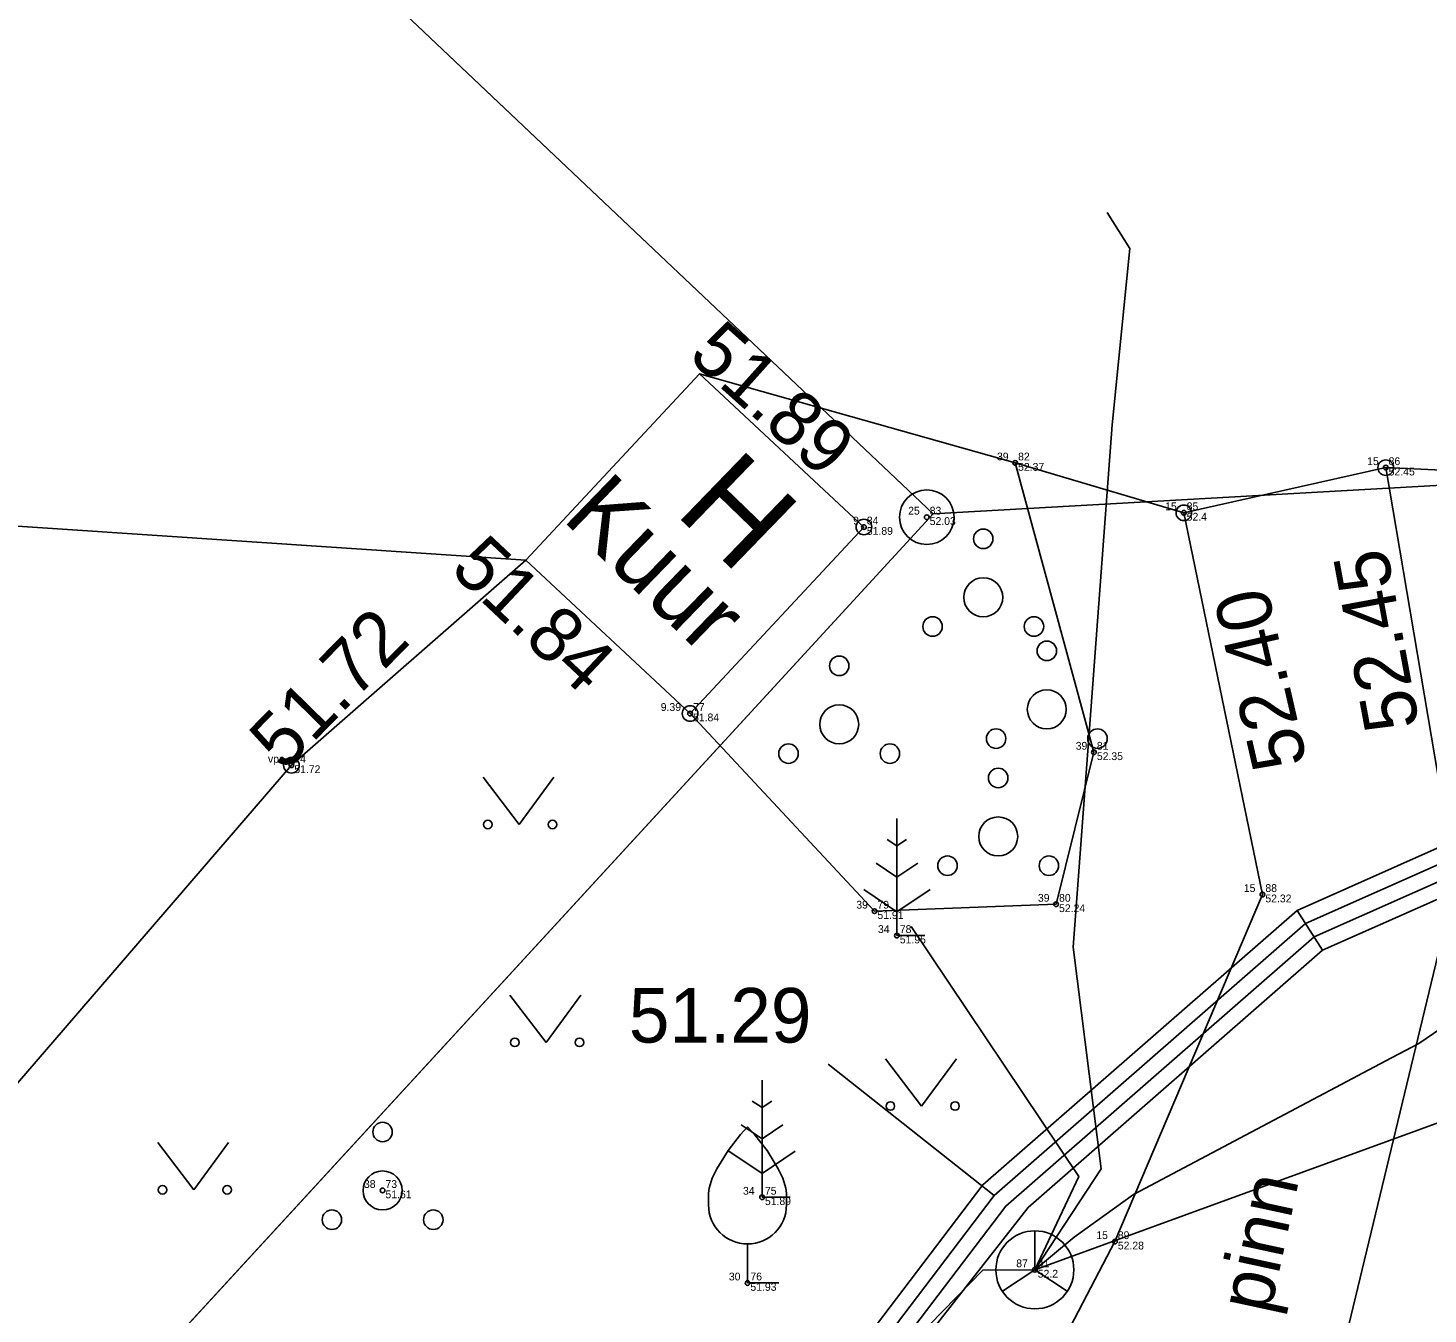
# Model space of a CAD drawing. Extents: x 543497 to 552146, y 6567125 to 6579845.
# Drawn here: x 546496.42 to 546514.37, y 6577831.22 to 6577847.71 of the extents above; entities that cross this region are included whole.
import ezdxf

# ---------------------------------------------------------------- set-up
doc = ezdxf.new("R2010")
doc.units = 0
for name, color, linetype in [('xref_Kangru tee 1_geodeesia$0$ABIJOONIS', 7, 'Continuous'), ('xref_Kangru tee 1_geodeesia$0$ELRAJATISMA', 7, 'Continuous'), ('xref_Kangru tee 1_geodeesia$0$HALJASTUS', 7, 'Continuous'), ('xref_Kangru tee 1_geodeesia$0$HOONE', 7, 'Continuous'), ('xref_Kangru tee 1_geodeesia$0$korgus-EH2000', 7, 'Continuous'), ('xref_Kangru tee 1_geodeesia$0$mootkood', 7, 'Continuous'), ('xref_Kangru tee 1_geodeesia$0$MOOTKORG-eh2000', 7, 'Continuous'), ('xref_Kangru tee 1_geodeesia$0$mootmpunkt', 7, 'Continuous'), ('xref_Kangru tee 1_geodeesia$0$MOOTNR', 7, 'Continuous'), ('xref_Kangru tee 1_geodeesia$0$MOOTPIIR', 7, 'Continuous'), ('xref_Kangru tee 1_geodeesia$0$MPKAABEL', 7, 'Continuous'), ('xref_Kangru tee 1_geodeesia$0$PIIR', 7, 'Continuous'), ('xref_Kangru tee 1_geodeesia$0$PIIRIMLEITUD', 7, 'Continuous'), ('xref_Kangru tee 1_geodeesia$0$PUU', 7, 'Continuous'), ('xref_Kangru tee 1_geodeesia$0$SIKAEV', 7, 'Continuous'), ('xref_Kangru tee 1_geodeesia$0$SITRASS', 7, 'Continuous'), ('xref_Kangru tee 1_geodeesia$0$TEE', 7, 'Continuous')]:
    doc.layers.add(name, color=color, linetype=linetype)

# ---------------------------------------------------------------- blocks, each defined once
blk = doc.blocks.new('xref_Kangru tee 1_geodeesia$0$SIKAEV')
for p, q in [((0, 1), (0, 0)), ((0, 0), (-0.83, -0.55)), ((0, 0), (0.83, -0.55))]:
    blk.add_line(p, q)
blk.add_circle((0, 0), 1)
blk = doc.blocks.new('xref_Kangru tee 1_geodeesia$0$PQQSAS')
for centre, radius in [((0, 1.5), 0.25), ((0, 0), 0.5), ((-1.3, -0.75), 0.25), ((1.3, -0.75), 0.25)]:
    blk.add_circle(centre, radius)
blk = doc.blocks.new('xref_Kangru tee 1_geodeesia$0$mand1')
for p, q in [((0, 3), (0, 0)), ((0, 2.3), (-0.249, 2.466)), ((0.249, 2.466), (0, 2.3)), ((0, 1.5), (-0.533, 1.855)), ((0.533, 1.855), (0, 1.5)), ((-0.849, 1.179), (0, 0.613)), ((0, 0.613), (0.849, 1.179)), ((0.72, 0), (0, 0))]:
    blk.add_line(p, q)
blk = doc.blocks.new('xref_Kangru tee 1_geodeesia$0$VILJA1')
for p, q in [((0, 0), (0, 1)), ((0.8, 0), (0, 0))]:
    blk.add_line(p, q)
for points in [[(-1, 2), (-1, 2.3), (-0.98, 2.43), (-0.91, 2.69), (-0.79, 2.93), (-0.5, 3.4), (-0.18, 3.81), (0, 4)], [(1, 2), (1, 2.3), (0.98, 2.43), (0.91, 2.69), (0.79, 2.93), (0.5, 3.4), (0.18, 3.81), (0, 4)]]:
    blk.add_lwpolyline(points)
blk.add_arc((0, 2), 1, 180, 0)
blk = doc.blocks.new('xref_Kangru tee 1_geodeesia$0$PMTORU')
blk.add_circle((0, 0), 0.7)
blk = doc.blocks.new('xref_Kangru tee 1_geodeesia$0$MURU')
for p, q in [((-0.927, 1.213), (0, 0)), ((0, 0), (0.891, 1.213))]:
    blk.add_line(p, q)
for centre in [(-0.802, 0), (0.856, 0)]:
    blk.add_circle(centre, 0.11)

msp = doc.modelspace()

# ---------------------------------------------------------------- linework, layer by layer
at = {"layer": 'xref_Kangru tee 1_geodeesia$0$ABIJOONIS'}
msp.add_lwpolyline([(546508.812, 6577832.742), (546506.684, 6577834.424)], dxfattribs=at)
at = {"layer": 'xref_Kangru tee 1_geodeesia$0$ELRAJATISMA'}
for points in [[(546512.696, 6577836.397), (546514.646, 6577837.264), (546525.645, 6577845.5), (546527.137, 6577846.751), (546527.843, 6577846.56), (546526.018, 6577845.029), (546514.952, 6577836.743), (546513.022, 6577835.886), (546512.696, 6577836.397)], [(546504.478, 6577826.48), (546507.219, 6577830.975), (546508.665, 6577832.879), (546512.696, 6577836.397), (546513.022, 6577835.886), (546509.246, 6577832.59), (546507.715, 6577830.636), (546504.991, 6577826.168), (546503.121, 6577825.158), (546503.766, 6577826.25), (546504.478, 6577826.48)]]:
    msp.add_lwpolyline(points, dxfattribs=at)
at = {"layer": 'xref_Kangru tee 1_geodeesia$0$HALJASTUS'}
for points in [[(546504.912, 6577838.921), (546507.277, 6577836.387), (546509.606, 6577836.475), (546510.091, 6577838.424), (546509.081, 6577842.133)], [(546483.928, 6577831.007), (546484.106, 6577832.259), (546490.129, 6577827.047), (546499.799, 6577838.257), (546502.804, 6577840.886)]]:
    msp.add_lwpolyline(points, dxfattribs=at)
at = {"layer": 'xref_Kangru tee 1_geodeesia$0$HOONE'}
msp.add_lwpolyline([(546505.033, 6577843.277), (546507.141, 6577841.312), (546504.912, 6577838.921), (546502.804, 6577840.886)], dxfattribs=at)
at = {"layer": 'xref_Kangru tee 1_geodeesia$0$korgus-EH2000'}
for centre in [(546513.833, 6577842.073), (546511.243, 6577841.494), (546507.141, 6577841.312), (546504.912, 6577838.921), (546499.799, 6577838.257)]:
    msp.add_circle(centre, 0.1, dxfattribs=at)
at = {"layer": 'xref_Kangru tee 1_geodeesia$0$mootmpunkt'}
for centre in [(546509.081, 6577842.133), (546513.833, 6577842.073), (546507.947, 6577841.438), (546511.243, 6577841.494), (546507.141, 6577841.312), (546504.912, 6577838.921), (546510.091, 6577838.424), (546499.799, 6577838.257), (546512.252, 6577836.6), (546507.277, 6577836.387), (546509.606, 6577836.475), (546507.564, 6577836.074), (546500.968, 6577832.806), (546505.834, 6577832.719), (546510.36, 6577832.15), (546509.333, 6577831.789), (546505.648, 6577831.62)]:
    msp.add_circle(centre, 0.03, dxfattribs=at)
at = {"layer": 'xref_Kangru tee 1_geodeesia$0$MOOTPIIR'}
msp.add_lwpolyline([(546524.807, 6577818.824), (546524.335, 6577820.155), (546523.257, 6577825.159), (546523.628, 6577826.051), (546521.953, 6577833.502), (546521.112, 6577836.894), (546520.061, 6577840.252), (546519.084, 6577842.675), (546518.786, 6577842.498), (546518.339, 6577842.354), (546515.541, 6577841.994), (546513.833, 6577842.073), (546511.243, 6577841.494), (546509.081, 6577842.133), (546505.033, 6577843.277), (546502.804, 6577840.886), (546478.391, 6577842.519)], dxfattribs=at)
at = {"layer": 'xref_Kangru tee 1_geodeesia$0$MPKAABEL'}
for points in [[(546527.321, 6577847.419), (546527.372, 6577846.687), (546525.769, 6577845.343), (546514.748, 6577837.09), (546512.804, 6577836.227), (546508.812, 6577832.742), (546507.384, 6577830.862), (546504.649, 6577826.376), (546503.269, 6577825.399)], [(546503.758, 6577826.154), (546504.82, 6577826.272), (546507.549, 6577830.749), (546508.959, 6577832.605), (546512.913, 6577836.056), (546514.85, 6577836.916), (546525.893, 6577845.186), (546527.457, 6577846.497), (546527.52, 6577846.865)]]:
    msp.add_lwpolyline(points, dxfattribs=at)
at = {"layer": 'xref_Kangru tee 1_geodeesia$0$PIIR'}
for points in [[(546044, 6578353.3), (546163.95, 6578208.05), (546259.8, 6578095.33), (546272.31, 6578081.21), (546307.56, 6578041.43), (546352.17, 6578005.12), (546393.84, 6577964.11), (546469.41, 6577900.33), (546488.79, 6577882.98), (546508.9, 6577863.97), (546517.98, 6577854.65), (546527.76, 6577842.6), (546508.03, 6577841.48), (546484.68, 6577863.57), (546483.99, 6577862.81), (546439.17, 6577910.04), (546353.06, 6577980.64), (546342.34, 6577986.89), (546303.57, 6578024.94), (546269.27, 6578063.09), (546244.31, 6578092.34), (546063, 6578304.76)], [(546455.94, 6577805.47), (546452.89, 6577819.28), (546448.94, 6577824.49), (546483.99, 6577862.81), (546484.68, 6577863.57), (546508.03, 6577841.48), (546479.51, 6577810.47), (546455.94, 6577805.47)], [(546508.03, 6577841.48), (546527.76, 6577842.6), (546535.64, 6577829.79), (546540.71, 6577817.81), (546551.12, 6577809.99), (546561.59, 6577802.16), (546622.52, 6577814.88), (546633.51, 6577792.62), (546608.95, 6577787.91), (546573.78, 6577780.87), (546521.59, 6577770.69), (546316.12, 6577725.86), (546173.38, 6577691.06), (546034.23, 6577654.21), (545899.95, 6577611.29), (545780.54, 6577566.57), (545623.97, 6577499.02), (545555.77, 6577467.67), (545385.83, 6577376.92), (545249.19, 6577295.85), (545250.22, 6577289.9), (544980.83, 6577118.49)], [(546117.94, 6577707.48), (546328.8, 6577761.79), (546320.77, 6577750.51), (546433.24, 6577777.18), (546446.51, 6577792.1), (546464.1, 6577793.71), (546479.51, 6577810.47), (546508.03, 6577841.48)]]:
    msp.add_lwpolyline(points, dxfattribs=at)
at = {"layer": 'xref_Kangru tee 1_geodeesia$0$SITRASS'}
for points in [[(546510.262, 6577845.344), (546510.55, 6577844.881), (546510.326, 6577842.622), (546509.825, 6577835.926), (546510.182, 6577833.084), (546509.333, 6577831.789)], [(546510.326, 6577842.622), (546510.55, 6577844.881), (546510.262, 6577845.344)], [(546509.333, 6577831.789), (546509.839, 6577832.208), (546510.596, 6577832.753), (546513.907, 6577834.506), (546514.257, 6577834.691), (546516.929, 6577836.511), (546521.829, 6577839.875), (546524.488, 6577842.205)], [(546525.051, 6577840.538), (546522.275, 6577838.519), (546516.571, 6577834.645), (546515.94, 6577834.27), (546515.428, 6577834.013), (546509.333, 6577831.789)], [(546509.333, 6577831.789), (546515.428, 6577834.013), (546516.571, 6577834.645), (546522.275, 6577838.519), (546525.051, 6577840.538)], [(546507.746, 6577836.19), (546509.895, 6577832.985), (546509.333, 6577831.789)], [(546441.003, 6577802.952), (546448.938, 6577804.593), (546449.988, 6577804.587), (546452.008, 6577803.679), (546454.595, 6577804.108), (546463.99, 6577805.757), (546472.578, 6577807.518), (546480.691, 6577809.331), (546489.752, 6577811.189), (546496.891, 6577812.816), (546497.942, 6577815.038), (546504.004, 6577824.544), (546504.927, 6577826.417), (546507.64, 6577830.733), (546508.664, 6577831.785), (546509.333, 6577831.789)]]:
    msp.add_lwpolyline(points, dxfattribs=at)
at = {"layer": 'xref_Kangru tee 1_geodeesia$0$TEE'}
msp.add_lwpolyline([(546513.833, 6577842.073), (546514.731, 6577836.776), (546513.19, 6577830.374), (546510.261, 6577825.752), (546507.884, 6577827.41), (546510.36, 6577832.15), (546512.252, 6577836.6), (546511.243, 6577841.494)], dxfattribs=at)

# ---------------------------------------------------------------- block references
at = {"layer": 'xref_Kangru tee 1_geodeesia$0$HALJASTUS', "xscale": 0.5, "yscale": 0.5}
for name, p in [('xref_Kangru tee 1_geodeesia$0$PQQSAS', (546508.671, 6577840.411)), ('xref_Kangru tee 1_geodeesia$0$PQQSAS', (546509.486, 6577838.974)), ('xref_Kangru tee 1_geodeesia$0$PQQSAS', (546506.824, 6577838.782)), ('xref_Kangru tee 1_geodeesia$0$PQQSAS', (546508.863, 6577837.345)), ('xref_Kangru tee 1_geodeesia$0$MURU', (546502.72, 6577837.498)), ('xref_Kangru tee 1_geodeesia$0$MURU', (546503.064, 6577834.705)), ('xref_Kangru tee 1_geodeesia$0$MURU', (546507.881, 6577833.889)), ('xref_Kangru tee 1_geodeesia$0$MURU', (546498.548, 6577832.815))]:
    msp.add_blockref(name, p, dxfattribs=at)
at = {"layer": 'xref_Kangru tee 1_geodeesia$0$PIIRIMLEITUD', "xscale": 0.5, "yscale": 0.5}
msp.add_blockref('xref_Kangru tee 1_geodeesia$0$PMTORU', (546507.947, 6577841.438), dxfattribs=at)
at = {"layer": 'xref_Kangru tee 1_geodeesia$0$PUU', "xscale": 0.5, "yscale": 0.5}
for name, p in [('xref_Kangru tee 1_geodeesia$0$mand1', (546507.564, 6577836.074)), ('xref_Kangru tee 1_geodeesia$0$mand1', (546505.834, 6577832.719)), ('xref_Kangru tee 1_geodeesia$0$PQQSAS', (546500.968, 6577832.806)), ('xref_Kangru tee 1_geodeesia$0$VILJA1', (546505.648, 6577831.62))]:
    msp.add_blockref(name, p, dxfattribs=at)
at = {"layer": 'xref_Kangru tee 1_geodeesia$0$SIKAEV', "xscale": 0.5, "yscale": 0.5}
msp.add_blockref('xref_Kangru tee 1_geodeesia$0$SIKAEV', (546509.333, 6577831.789), dxfattribs=at)

# ---------------------------------------------------------------- texts
at = {"layer": 'xref_Kangru tee 1_geodeesia$0$ABIJOONIS'}
msp.add_text('51.29', height=0.7, dxfattribs=at).set_placement((546504.126, 6577834.702))
at = {"layer": 'xref_Kangru tee 1_geodeesia$0$HOONE'}
for s, height, rotation, p in [('H', 1.2, 315.9325, (546504.7, 6577841.493)), ('Kuur', 0.9, 315.8914, (546503.257, 6577841.413))]:
    msp.add_text(s, height=height, rotation=rotation, dxfattribs=at).set_placement(p)
at = {"layer": 'xref_Kangru tee 1_geodeesia$0$korgus-EH2000'}
for s, rotation, p in [(' 51.89 ', 318.1619, (546504.675, 6577843.657)), (' 51.84 ', 316.7848, (546501.627, 6577840.927)), (' 52.45 ', 100.4894, (546514.314, 6577838.508)), (' 52.40 ', 102.9516, (546512.887, 6577838.035)), (' 51.72 ', 45.5264, (546499.52, 6577837.979))]:
    msp.add_text(s, height=0.7, rotation=rotation, dxfattribs=at).set_placement(p)
at = {"layer": 'xref_Kangru tee 1_geodeesia$0$mootkood'}
for s, p in [(' 39', (546508.81, 6577842.166)), (' 15', (546513.557, 6577842.106)), (' 25', (546507.671, 6577841.471)), (' 15', (546510.967, 6577841.527)), (' 9', (546506.965, 6577841.345)), (' 9.39', (546504.498, 6577838.954)), (' 39', (546509.82, 6577838.457)), (' vpa', (546499.461, 6577838.29)), (' 15', (546511.976, 6577836.633)), (' 39', (546509.335, 6577836.508)), (' 39', (546507.006, 6577836.42)), (' 34', (546507.283, 6577836.107)), (' 38', (546500.692, 6577832.839)), (' 34', (546505.553, 6577832.752)), (' 15', (546510.084, 6577832.183)), (' 87', (546509.057, 6577831.822)), (' 30', (546505.372, 6577831.653))]:
    msp.add_text(s, height=0.1, dxfattribs=at).set_placement(p)
at = {"layer": 'xref_Kangru tee 1_geodeesia$0$MOOTKORG-eh2000'}
for s, p in [(' 52.37', (546509.081, 6577842.033)), (' 52.45', (546513.833, 6577841.973)), (' 52.03', (546507.947, 6577841.338)), (' 52.4', (546511.243, 6577841.394)), (' 51.89', (546507.141, 6577841.212)), (' 51.84', (546504.912, 6577838.821)), (' 52.35', (546510.091, 6577838.324)), (' 51.72', (546499.799, 6577838.157)), (' 52.32', (546512.252, 6577836.5)), (' 51.91', (546507.277, 6577836.287)), (' 52.24', (546509.606, 6577836.375)), (' 51.95', (546507.564, 6577835.974)), (' 51.61', (546500.968, 6577832.706)), (' 51.89', (546505.834, 6577832.619)), (' 52.28', (546510.36, 6577832.05)), (' 52.2', (546509.333, 6577831.689)), (' 51.93', (546505.648, 6577831.52))]:
    msp.add_text(s, height=0.1, dxfattribs=at).set_placement(p)
at = {"layer": 'xref_Kangru tee 1_geodeesia$0$MOOTNR'}
for s, p in [(' 82', (546509.081, 6577842.166)), (' 86', (546513.833, 6577842.106)), (' 83', (546507.947, 6577841.471)), (' 85', (546511.243, 6577841.527)), (' 84', (546507.141, 6577841.345)), (' 77', (546504.912, 6577838.954)), (' 81', (546510.091, 6577838.457)), (' 74', (546499.799, 6577838.29)), (' 88', (546512.252, 6577836.633)), (' 80', (546509.606, 6577836.508)), (' 79', (546507.277, 6577836.42)), (' 78', (546507.564, 6577836.107)), (' 73', (546500.968, 6577832.839)), (' 75', (546505.834, 6577832.752)), (' 89', (546510.36, 6577832.183)), (' 41', (546509.333, 6577831.822)), (' 76', (546505.648, 6577831.653))]:
    msp.add_text(s, height=0.1, dxfattribs=at).set_placement(p)
at = {"layer": 'xref_Kangru tee 1_geodeesia$0$TEE'}
msp.add_text('pinn', height=0.7, rotation=77.8132, dxfattribs=at).set_placement((546512.347, 6577831.207))

doc.saveas('drawing.dxf')
